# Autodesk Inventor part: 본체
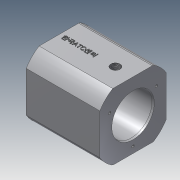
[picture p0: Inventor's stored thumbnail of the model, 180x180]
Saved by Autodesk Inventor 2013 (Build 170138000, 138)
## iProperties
Created: 2020-02
Part Number: 본체
Material: 알루미늄 6061
Document SubType Name: Modeling
Designer: CADCOM
Density: 2.71 g/cm^3
Mass: 540.135 g
Surface Area: 341.963 cm^2
Volume: 199.312 cm^3
Author: CADCOM
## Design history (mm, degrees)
sketch "스케치1"
  geometry: L1 (-32, -32)-(32, -32); L2 (32, -32)-(32, 32); L3 (32, 32)-(-32, 32); L4 (-32, 32)-(-32, -32); L5 (-32, -32)-(32, 32); L6 (32, -32)-(-32, 32); 1 further point
  constraints: 12 end point, 2 midpoint, 2 parallel, 1 horizontal, 1 perpendicular
  dimensions: "d0" = 64 distance of L3.end L2.end; "d1" = 64 distance of L2.end L1.end
extrude "돌출1" new body sketch "스케치1" distance "d3" = 71; taper "d4" = 0 deg
sketch "스케치2" dims "d5" = 75
  geometry: L1 (-32, -32)-(32, -32) reference; L2 (32, -32)-(32, 32) reference; L3 (32, 32)-(-32, 32) reference; L4 (-32, 19.551)-(-32, -19.551); L5 (-32, 19.551)-(-32, 32); L6 (-32, 32)-(-19.551, 32); L7 (-32, -19.551)-(-32, -32); L8 (-32, -32)-(-19.551, -32); L9 (19.551, -32)-(32, -32); L10 (32, -32)-(32, -19.551); L11 (32, 19.551)-(32, 32); L12 (32, 32)-(19.551, 32); 2 further points
  constraints: 18 end point, 6 point on line, 3 collinear, 1 coincident, 1 perpendicular, 10 other
extrude "돌출2" cut sketch "스케치2" stored distance "d6" = 71; taper "d7" = 0 deg
sketch "스케치3"
  geometry: C1 r 20 at (0, 0); A1 r 37.5 centre (0, 0) between (19.551, -32) and (32, -19.551) reference
  constraints: 1 centre point, 1 coincident
  dimensions: "d8" = 40 diameter of C1
extrude "돌출3" cut sketch "스케치3" distance "d9" = 62; taper "d10" = 0 deg
sketch "스케치4"
  geometry: C1 r 14 at (0, 0); A1 r 37.5 centre (0, 0) between (32, 19.551) and (19.551, 32) reference
  constraints: 1 centre point, 1 coincident
  dimensions: "d11" = 28 diameter of C1
extrude "돌출4" join sketch "스케치4" distance "d12" = 12; taper "d13" = 0 deg
sketch "스케치5"
  geometry: C1 r 14 at (0, 0) reference; 1 further point
  constraints: 1 coincident
hole "구멍1" sketch "스케치5" at (0, 0) diameter "d14" = 8.917; stored, may be unused: countersink angle "d18" = 90 deg, drill point angle "d20" = 118 deg; dims "d15" = 14, "d16" = 4, "d17" = 2, "d19" = 17
node "작업 평면1"
sketch "스케치7"
  geometry: C1 r 2 at (0, 0); 1 further point
  constraints: 1 centre point, 1 coincident
  dimensions: "d23" = 4 diameter of C1
extrude "돌출5" cut sketch "스케치7" distance "d24" = 12; taper "d25" = 0 deg
sketch "스케치8"
  geometry: L1 (19.551, 32)-(-19.551, 32) reference; L2 (0, 0)-(0, 26); A1 r 37.5 centre (0, 0) between (32, 19.551) and (19.551, 32) reference; 1 further point
  constraints: 2 end point, 1 coincident, 1 perpendicular
  dimensions: "d26" = 26 distance of L2.start L2.end
hole "구멍2" sketch "스케치8" at (0, 26) diameter "d27" = 3.242; stored, may be unused: countersink angle "d31" = 90 deg, drill point angle "d33" = 118 deg; dims "d28" = 10, "d29" = 4, "d30" = 2, "d32" = 12
sketch "스케치9"
  geometry: L1 (39.102, 0)-(0, 0) reference; L2 (19.551, 0)-(19.551, 17); 1 further point
  constraints: 2 end point, 1 coincident, 1 perpendicular
  dimensions: "d37" = 17 distance of L2.start L2.end
hole "구멍3" sketch "스케치9" at (19.551, 17) diameter "d38" = 8.917; stored, may be unused: countersink angle "d42" = 90 deg, drill point angle "d44" = 118 deg; dims "d39" = 6, "d40" = 4, "d41" = 2, "d43" = 9
sketch "스케치13"
  geometry: L1 (19.551, 32)-(-19.551, 32) reference; L2 (-19.551, -32)-(19.551, -32) reference; L3 (32, -19.551)-(32, 19.551) reference; L4 (0, 0)-(0, 32); L5 (0, 0)-(-32.476, 18.75); L6 (0, 0)-(32, 18.475); L7 (0, 0)-(0, -32); A1 r 37.5 centre (0, 0) between (-19.551, 32) and (-32, 19.551) reference; A2 r 37.5 centre (0, 0) between (19.551, -32) and (32, -19.551) reference; A3 r 26 centre (0, 0) between (-22.517, 13) and (22.517, 13); 1 further point
  constraints: 8 end point, 4 point on circle, 4 point on line, 2 midpoint, 1 centre point, 1 coincident
  dimensions: "d56" = 52 diameter of A3; "d57" = 60 deg angle of L4 L5; "d59" = 60 deg angle of L6 L4
hole "구멍4" sketch "스케치13" at (-22.517, 13), (22.517, 13), (0, -26) diameter "d61" = 2.459; stored, may be unused: countersink angle "d65" = 90 deg, drill point angle "d67" = 118 deg; dims "d62" = 10, "d63" = 4, "d64" = 2, "d66" = 12
chamfer "모따기1" distance "d68" = 1.8; stored, may be unused: second distance "d69" = 2, angle "d70" = 15 deg
chamfer "모따기2" distance "d71" = 1; stored, may be unused: second distance "d72" = 2, angle "d73" = 15 deg
chamfer "모따기3" distance "d74" = 1; stored, may be unused: second distance "d75" = 2, angle "d76" = 15 deg
sketch "스케치14"
  geometry: L1 (0, 71)-(38.102, 71) reference; L2 (0, 71)-(0, 0) reference; 2 further points
  constraints: 1 other
  dimensions: "d77" = 20 distance from line of point (19.051, 51) L1; "d78" = 19.051 distance from line of L2 point (19.051, 51)
feature "엠보싱1" sketch "스케치14" dims "d79" = 0.5, "d80" = 0
node "작업 평면5"
sketch "스케치15"
  geometry: L1 (0, 0)-(0, -17); C1 r 2 at (0, -17)
  constraints: 2 end point, 1 centre point, 1 coincident, 1 vertical
  dimensions: "d82" = 17 distance of L1.start L1.end; "d83" = 4 diameter of C1
extrude "돌출7" cut sketch "스케치15" stored distance "d84" = 35; taper "d85" = 0 deg
node "솔리드1"
pattern_circular "원형 패턴1" dims angle "d35" = 360 deg
other parameters: "d22" = -62
